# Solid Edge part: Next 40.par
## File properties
Title: Next 40 40x40 cm
Author: DESYS
Template: Normal.par
Last saved by: s.pallini
Revision: 10
Application: Solid Edge
Tipo di contenuto documento: 0
Precisione: 0,990
Document Number: 8306
Revision: 0
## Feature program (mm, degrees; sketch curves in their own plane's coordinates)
sketch for "unnamed Protrusion 1" plane through (0, 0, 0) normal (0, 0, 1) x-axis (1, 0, 0)
  line (-103.5, -203.5) -> (103.5, -203.5)
  arc centre (103.5, -103.5) radius 100 from (103.5, -203.5) to (203.5, -103.5) ccw
  line (203.5, -103.5) -> (203.5, 103.5)
  arc centre (103.5, 103.5) radius 100 from (103.5, 203.5) to (203.5, 103.5) cw
  line (103.5, 203.5) -> (-103.5, 203.5)
  arc centre (-103.5, 103.5) radius 100 from (-103.5, 203.5) to (-203.5, 103.5) ccw
  line (-203.5, 103.5) -> (-203.5, -103.5)
  arc centre (-103.5, -103.5) radius 100 from (-203.5, -103.5) to (-103.5, -203.5) ccw
  dimension (linear) = 103.5
  dimension (linear) = 203.5
extrude "unnamed Protrusion 1" add finite 55 along -normal
sketch for "ExtrudedProtrusion_2" plane through (0, 0, 0) normal (0, 0, 1) x-axis (1, 0, 0)
  line (-94.5, -184.5) -> (94.5, -184.5)
  arc centre (94.5, -94.5) radius 90 from (184.5, -94.5) to (94.5, -184.5) cw
  line (184.5, -94.5) -> (184.5, 94.5)
  arc centre (94.5, 94.5) radius 90 from (94.5, 184.5) to (184.5, 94.5) cw
  line (94.5, 184.5) -> (-94.5, 184.5)
  arc centre (-94.5, 94.5) radius 90 from (-94.5, 184.5) to (-184.5, 94.5) ccw
  line (-184.5, 94.5) -> (-184.5, -94.5)
  arc centre (-94.5, -94.5) radius 90 from (-184.5, -94.5) to (-94.5, -184.5) ccw
  dimension (linear) = 94.5
  dimension (linear) = 184.5
extrude "ExtrudedProtrusion_2" add finite 133 along -normal
sketch for "ExtrudedCutout_1" plane through (0, 0, 0) normal (0, 0, 1) x-axis (1, 0, 0)
  line (-112, -162) -> (112, -162)
  arc centre (112, -112) radius 50 from (162, -112) to (112, -162) cw
  line (162, -112) -> (162, 112)
  arc centre (112, 112) radius 50 from (112, 162) to (162, 112) cw
  line (112, 162) -> (-112, 162)
  arc centre (-112, 112) radius 50 from (-112, 162) to (-162, 112) ccw
  line (-162, 112) -> (-162, -112)
  arc centre (-112, -112) radius 50 from (-162, -112) to (-112, -162) ccw
  dimension (linear) = 112
  dimension (linear) = 162
extrude "ExtrudedCutout_1" cut finite 100 along -normal  Treatment1_DraftAngle = 10 deg
fillet "Rotondo_1" radius 30
sketch for "Foro_1" plane through (0, 0, -100) normal (0, 0, 1) x-axis (1, 0, 0)
  hole centre (0, 0) bore radius 25
hole "Foro_1" diameter 50 through
fillet "Rotondo_2" radius 15
sketch for "ExtrudedCutout_2" #1 plane through (0, 0, -133) normal (0, 0, -1) x-axis (0, 1, 0)
  circle centre (0, 0) radius 35
sketch for "ExtrudedCutout_2" #2 plane through (0, 0, -133) normal (0, 0, -1) x-axis (0, 1, 0)
  line (-100, -145) -> (100, -145)
  arc centre (100, -100) radius 45 from (100, -145) to (145, -100) ccw
  line (145, -100) -> (145, 100)
  arc centre (100, 100) radius 45 from (100, 145) to (145, 100) cw
  line (100, 145) -> (-100, 145)
  arc centre (-100, 100) radius 45 from (-100, 145) to (-145, 100) ccw
  line (-145, 100) -> (-145, -100)
  arc centre (-100, -100) radius 45 from (-145, -100) to (-100, -145) ccw
  dimension (linear) = 100
  dimension (linear) = 145
extrude "ExtrudedCutout_2" cut finite 22 along -normal  DraftAngle = 20 deg
fillet "Rotondo_4" radius 10
sketch for "unnamed Protrusion 2" #1 plane through (0, 0, -133) normal (0, 0, -1) x-axis (0, 1, 0)
  line (-112, -148.7385) -> (112, -148.7385)
  arc centre (112, -112) radius 36.7385 from (112, -148.7385) to (148.7385, -112) ccw
  line (148.7385, -112) -> (148.7385, 112)
  arc centre (112, 112) radius 36.7385 from (148.7385, 112) to (112, 148.7385) ccw
  line (112, 148.7385) -> (-112, 148.7385)
  arc centre (-112, 112) radius 36.7385 from (-112, 148.7385) to (-148.7385, 112) ccw
  line (-148.7385, 112) -> (-148.7385, -112)
  arc centre (-112, -112) radius 36.7385 from (-148.7385, -112) to (-112, -148.7385) ccw
sketch for "unnamed Protrusion 2" #2 plane through (0, 0, -133) normal (0, 0, -1) x-axis (0, 1, 0)
extrude "unnamed Protrusion 2" add through along -normal
fillet "Rotondo_3" radius 10
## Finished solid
Body 1: solid body, 94 faces, 211 edges, 120 vertices.
  Faces by surface: cylinder 37, torus 27, plane 21, cone 9
  Edges by curve: circle 111, line 84, intersection 16
Bounding box of the edges (mm; curved faces can reach further): 407.000 x 407.000 x 133.000, from (-203.5, -203.5, -133) to (203.5, 203.5, 0).
Cylindrical faces by radius (mm): R10 x20, R25 x1, R30 x4, R36.7385 x8, R100 x4
Conical faces (half-angle, radius in mm at the cone's reference point): 10 deg R50 x4, 20 deg R35 x1, 20 deg R45 x4
Toroidal faces (ring radius, tube radius in mm): R7.1943 r30 x4, R27.9979 r10 x1, R29.9906 r10 x4, R40 r15 x1, R50.0094 r10 x1, R52.0021 r10 x4, R58.391 r10 x4, R90 r10 x8
Planar faces by outward normal: +x 2, +y 2, +z 2, -x 2, -y 2, -z 3, oblique 8
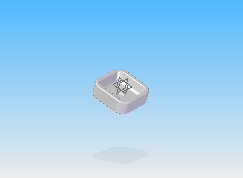
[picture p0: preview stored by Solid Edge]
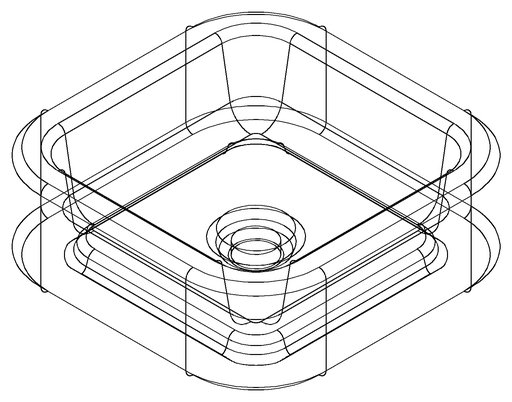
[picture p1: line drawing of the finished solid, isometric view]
